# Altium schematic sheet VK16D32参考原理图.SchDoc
size A4
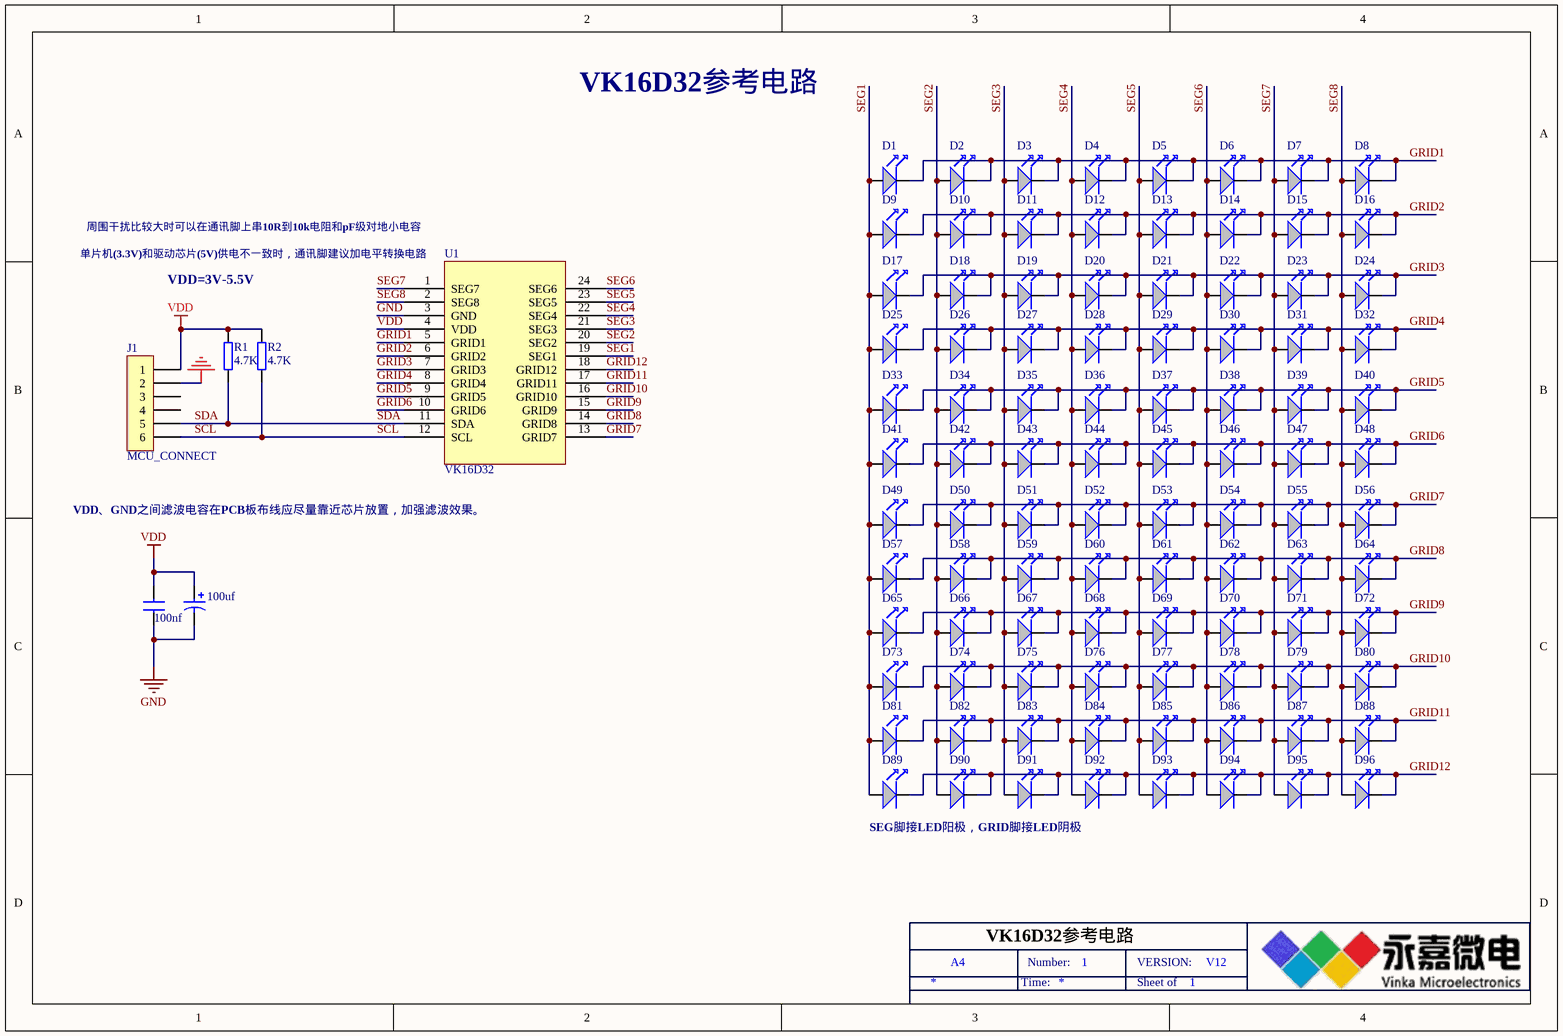
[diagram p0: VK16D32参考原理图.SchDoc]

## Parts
100nf  CAP  (value not drawn)
100uf  CAP2  (value not drawn)
D1  (no value)  [1206-LED]
D2  (no value)  [1206-LED]
D3  (no value)  [1206-LED]
D4  (no value)  [1206-LED]
D5  (no value)  [1206-LED]
D6  (no value)  [1206-LED]
D7  (no value)  [1206-LED]
D8  (no value)  [1206-LED]
D9  (no value)  [1206-LED]
D10  (no value)  [1206-LED]
D11  (no value)  [1206-LED]
D12  (no value)  [1206-LED]
D13  (no value)  [1206-LED]
D14  (no value)  [1206-LED]
D15  (no value)  [1206-LED]
D16  (no value)  [1206-LED]
D17  (no value)  [1206-LED]
D18  (no value)  [1206-LED]
D19  (no value)  [1206-LED]
D20  (no value)  [1206-LED]
D21  (no value)  [1206-LED]
D22  (no value)  [1206-LED]
D23  (no value)  [1206-LED]
D24  (no value)  [1206-LED]
D25  (no value)  [1206-LED]
D26  (no value)  [1206-LED]
D27  (no value)  [1206-LED]
D28  (no value)  [1206-LED]
D29  (no value)  [1206-LED]
D30  (no value)  [1206-LED]
D31  (no value)  [1206-LED]
D32  (no value)  [1206-LED]
D33  (no value)  [1206-LED]
D34  (no value)  [1206-LED]
D35  (no value)  [1206-LED]
D36  (no value)  [1206-LED]
D37  (no value)  [1206-LED]
D38  (no value)  [1206-LED]
D39  (no value)  [1206-LED]
D40  (no value)  [1206-LED]
D41  (no value)  [1206-LED]
D42  (no value)  [1206-LED]
D43  (no value)  [1206-LED]
D44  (no value)  [1206-LED]
D45  (no value)  [1206-LED]
D46  (no value)  [1206-LED]
D47  (no value)  [1206-LED]
D48  (no value)  [1206-LED]
D49  (no value)  [1206-LED]
D50  (no value)  [1206-LED]
D51  (no value)  [1206-LED]
D52  (no value)  [1206-LED]
D53  (no value)  [1206-LED]
D54  (no value)  [1206-LED]
D55  (no value)  [1206-LED]
D56  (no value)  [1206-LED]
D57  (no value)  [1206-LED]
D58  (no value)  [1206-LED]
D59  (no value)  [1206-LED]
D60  (no value)  [1206-LED]
D61  (no value)  [1206-LED]
D62  (no value)  [1206-LED]
D63  (no value)  [1206-LED]
D64  (no value)  [1206-LED]
D65  (no value)  [1206-LED]
D66  (no value)  [1206-LED]
D67  (no value)  [1206-LED]
D68  (no value)  [1206-LED]
D69  (no value)  [1206-LED]
D70  (no value)  [1206-LED]
D71  (no value)  [1206-LED]
D72  (no value)  [1206-LED]
D73  (no value)  [1206-LED]
D74  (no value)  [1206-LED]
D75  (no value)  [1206-LED]
D76  (no value)  [1206-LED]
D77  (no value)  [1206-LED]
D78  (no value)  [1206-LED]
D79  (no value)  [1206-LED]
D80  (no value)  [1206-LED]
D81  (no value)  [1206-LED]
D82  (no value)  [1206-LED]
D83  (no value)  [1206-LED]
D84  (no value)  [1206-LED]
D85  (no value)  [1206-LED]
D86  (no value)  [1206-LED]
D87  (no value)  [1206-LED]
D88  (no value)  [1206-LED]
D89  (no value)  [1206-LED]
D90  (no value)  [1206-LED]
D91  (no value)  [1206-LED]
D92  (no value)  [1206-LED]
D93  (no value)  [1206-LED]
D94  (no value)  [1206-LED]
D95  (no value)  [1206-LED]
D96  (no value)  [1206-LED]
J1  MCU_CONNECT
R1  4.7K  [0603-R]
R2  4.7K  [0603-R]
U1  VK16D32

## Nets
GND: 100nf.2 100uf.2 J1.2 U1.3(GND)
VDD: 100nf.1 100uf.1 J1.1 R1.1 R2.1 U1.4(VDD)
GRID1: D1.2 D2.2 D3.2 D4.2 D5.2 D6.2 D7.2 D8.2 U1.5(GRID1)
GRID2: D9.2 D10.2 D11.2 D12.2 D13.2 D14.2 D15.2 D16.2 U1.6(GRID2)
GRID3: D17.2 D18.2 D19.2 D20.2 D21.2 D22.2 D23.2 D24.2 U1.7(GRID3)
GRID4: D25.2 D26.2 D27.2 D28.2 D29.2 D30.2 D31.2 D32.2 U1.8(GRID4)
GRID5: D33.2 D34.2 D35.2 D36.2 D37.2 D38.2 D39.2 D40.2 U1.9(GRID5)
GRID6: D41.2 D42.2 D43.2 D44.2 D45.2 D46.2 D47.2 D48.2 U1.10(GRID6)
GRID7: D49.2 D50.2 D51.2 D52.2 D53.2 D54.2 D55.2 D56.2 U1.13(GRID7)
GRID8: D57.2 D58.2 D59.2 D60.2 D61.2 D62.2 D63.2 D64.2 U1.14(GRID8)
GRID9: D65.2 D66.2 D67.2 D68.2 D69.2 D70.2 D71.2 D72.2 U1.15(GRID9)
GRID10: D73.2 D74.2 D75.2 D76.2 D77.2 D78.2 D79.2 D80.2 U1.16(GRID10)
GRID11: D81.2 D82.2 D83.2 D84.2 D85.2 D86.2 D87.2 D88.2 U1.17(GRID11)
GRID12: D89.2 D90.2 D91.2 D92.2 D93.2 D94.2 D95.2 D96.2 U1.18(GRID12)
SCL: J1.6 R2.2 U1.12(SCL)
SDA: J1.5 R1.2 U1.11(SDA)
SEG1: D1.1 D9.1 D17.1 D25.1 D33.1 D41.1 D49.1 D57.1 D65.1 D73.1 D81.1 D89.1 U1.19(SEG1)
SEG2: D2.1 D10.1 D18.1 D26.1 D34.1 D42.1 D50.1 D58.1 D66.1 D74.1 D82.1 D90.1 U1.20(SEG2)
SEG3: D3.1 D11.1 D19.1 D27.1 D35.1 D43.1 D51.1 D59.1 D67.1 D75.1 D83.1 D91.1 U1.21(SEG3)
SEG4: D4.1 D12.1 D20.1 D28.1 D36.1 D44.1 D52.1 D60.1 D68.1 D76.1 D84.1 D92.1 U1.22(SEG4)
SEG5: D5.1 D13.1 D21.1 D29.1 D37.1 D45.1 D53.1 D61.1 D69.1 D77.1 D85.1 D93.1 U1.23(SEG5)
SEG6: D6.1 D14.1 D22.1 D30.1 D38.1 D46.1 D54.1 D62.1 D70.1 D78.1 D86.1 D94.1 U1.24(SEG6)
SEG7: D7.1 D15.1 D23.1 D31.1 D39.1 D47.1 D55.1 D63.1 D71.1 D79.1 D87.1 D95.1 U1.1(SEG7)
SEG8: D8.1 D16.1 D24.1 D32.1 D40.1 D48.1 D56.1 D64.1 D72.1 D80.1 D88.1 D96.1 U1.2(SEG8)

Not connected (* = marked no-connect by the designer): J1 3 4

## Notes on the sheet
- VK16D32参考电路
- 周围干扰比较大时可以在通讯脚上串10R到10k电阻和pF级对地小电容
- 单片机(3.3V)和驱动芯片(5V)供电不一致时，通讯脚建议加电平转换电路
- VDD=3V-5.5V
- VDD、GND之间滤波电容在PCB板布线应尽量靠近芯片放置，加强滤波效果。
- SEG脚接LED阳极，GRID脚接LED阴极
- A4
- Time:
- Number:
- 1
- Sheet of
- VERSION:
- V12

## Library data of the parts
100nf = CAP: Capacitor
100uf = CAP2: Bi-Polar Capacitor
D1-D96 = LED: Text Field1: 30; Text Field2: 20
J1 = CON6: Connector
R1 R2 = RES: Resistor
